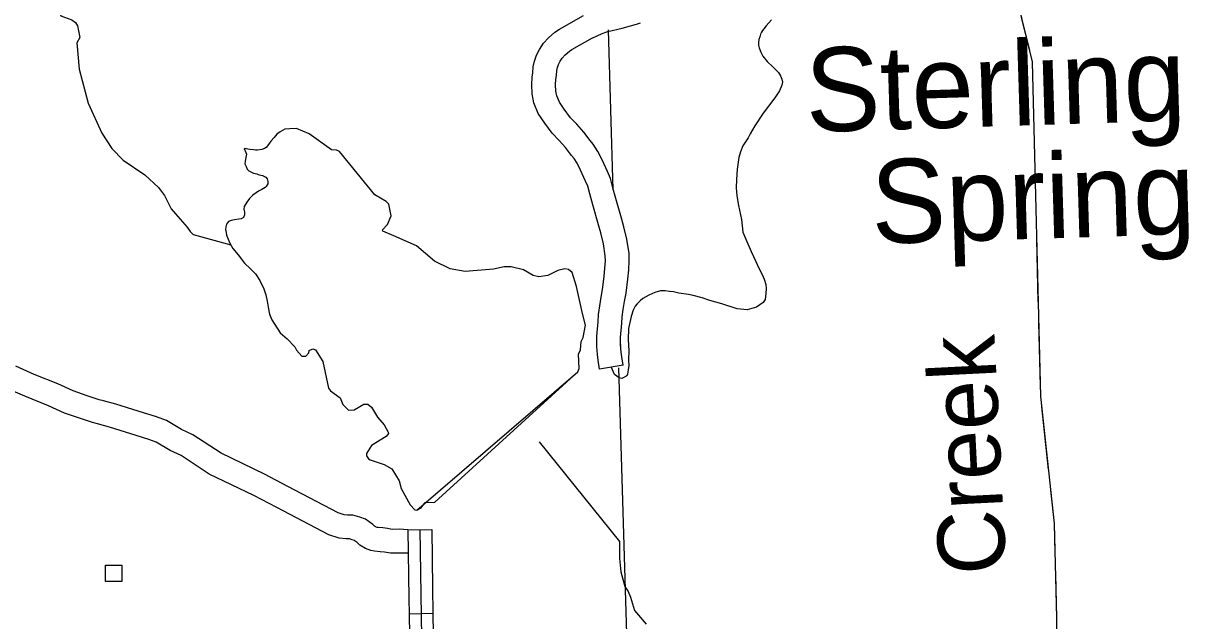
# Model space of a CAD drawing. Extents: x 1671357 to 13005564, y 567358 to 14261451.
# Drawn here: x 12758310.69 to 12758324.59, y 14259899.82 to 14259906.94 of the extents above; entities that cross this region are included whole.
import ezdxf

# ---------------------------------------------------------------- set-up
doc = ezdxf.new("R2010")
doc.units = 0
for name, color, linetype in [('24', 7, 'Continuous'), ('31', 7, 'Continuous'), ('32', 7, 'Continuous'), ('35', 7, 'Continuous'), ('43', 7, 'Continuous'), ('46', 7, 'Continuous'), ('5', 7, 'Continuous'), ('51', 7, 'Continuous'), ('56', 7, 'Continuous')]:
    doc.layers.add(name, color=color, linetype=linetype)

msp = doc.modelspace()

# ---------------------------------------------------------------- linework, layer by layer
at = {"layer": '31'}
msp.add_lwpolyline([(12758315.41, 14259900.907), (12758315.461, 14259897.56), (12758315.42, 14259897.511), (12758315.341, 14259897.481), (12758313.018, 14259897.398), (12758306.475, 14259897.154)], dxfattribs=at)
at = {"layer": '32'}
for p, q in [((12758315.267, 14259900.905), (12758315.552, 14259900.91)), ((12758315.283, 14259899.905), (12758315.567, 14259899.91))]:
    msp.add_line(p, q, dxfattribs=at)
for points in [[(12758315.267, 14259900.905), (12758315.28, 14259900.085)], [(12758315.552, 14259900.91), (12758315.562, 14259900.211)], [(12758315.562, 14259900.211), (12758315.567, 14259899.91)], [(12758315.28, 14259900.085), (12758315.283, 14259899.905)], [(12758315.567, 14259899.91), (12758315.582, 14259898.912)], [(12758315.283, 14259899.905), (12758315.295, 14259899.137)]]:
    msp.add_lwpolyline(points, dxfattribs=at)
at = {"layer": '35'}
for points in [[(12758311.037, 14259907.136), (12758311.075, 14259907.128), (12758311.111, 14259907.092), (12758311.132, 14259907.028), (12758311.263, 14259906.98), (12758311.308, 14259906.948), (12758311.333, 14259906.911), (12758311.357, 14259906.772), (12758311.324, 14259906.709), (12758311.349, 14259906.393), (12758311.457, 14259905.987), (12758311.62, 14259905.631), (12758311.741, 14259905.45), (12758311.874, 14259905.311), (12758312.134, 14259905.134), (12758312.297, 14259904.983), (12758312.366, 14259904.887), (12758312.448, 14259904.731), (12758312.498, 14259904.669), (12758312.64, 14259904.509), (12758312.672, 14259904.459), (12758312.708, 14259904.423), (12758313.16, 14259904.299)], [(12758314.092, 14259905.624), (12758313.94, 14259905.685), (12758313.863, 14259905.683), (12758313.804, 14259905.677), (12758313.745, 14259905.646), (12758313.708, 14259905.618), (12758313.673, 14259905.581), (12758313.635, 14259905.537), (12758313.608, 14259905.496), (12758313.578, 14259905.459), (12758313.559, 14259905.449), (12758313.529, 14259905.438), (12758313.476, 14259905.427), (12758313.452, 14259905.428), (12758313.429, 14259905.431), (12758313.385, 14259905.436), (12758313.316, 14259905.447), (12758313.339, 14259905.402), (12758313.346, 14259905.38), (12758313.338, 14259905.341), (12758313.328, 14259905.299), (12758313.325, 14259905.265), (12758313.34, 14259905.235), (12758313.353, 14259905.2), (12758313.374, 14259905.181), (12758313.403, 14259905.167), (12758313.428, 14259905.155), (12758313.467, 14259905.147), (12758313.486, 14259905.14), (12758313.515, 14259905.132), (12758313.536, 14259905.127), (12758313.549, 14259905.122), (12758313.561, 14259905.116), (12758313.576, 14259905.108), (12758313.59, 14259905.087), (12758313.599, 14259905.053), (12758313.598, 14259905.027), (12758313.581, 14259904.996), (12758313.568, 14259904.984), (12758313.529, 14259904.958), (12758313.49, 14259904.939), (12758313.46, 14259904.921), (12758313.422, 14259904.893), (12758313.381, 14259904.853), (12758313.349, 14259904.81), (12758313.319, 14259904.756), (12758313.314, 14259904.725), (12758313.32, 14259904.689), (12758313.321, 14259904.657), (12758313.311, 14259904.624), (12758313.283, 14259904.61), (12758313.255, 14259904.605), (12758313.204, 14259904.599), (12758313.181, 14259904.596), (12758313.162, 14259904.592), (12758313.132, 14259904.577), (12758313.107, 14259904.548), (12758313.107, 14259904.546), (12758313.097, 14259904.515), (12758313.094, 14259904.483), (12758313.102, 14259904.447), (12758313.108, 14259904.415), (12758313.126, 14259904.366), (12758313.146, 14259904.322), (12758313.183, 14259904.258), (12758313.245, 14259904.181), (12758313.322, 14259904.083), (12758313.391, 14259904.016), (12758313.415, 14259903.992), (12758313.453, 14259903.954), (12758313.503, 14259903.876), (12758313.55, 14259903.777), (12758313.576, 14259903.704), (12758313.59, 14259903.628), (12758313.603, 14259903.557), (12758313.621, 14259903.474), (12758313.648, 14259903.408), (12758313.748, 14259903.253), (12758313.829, 14259903.18)], [(12758314.092, 14259905.624), (12758313.94, 14259905.685), (12758313.863, 14259905.683), (12758313.804, 14259905.677), (12758313.745, 14259905.646), (12758313.708, 14259905.618), (12758313.673, 14259905.581), (12758313.635, 14259905.537), (12758313.608, 14259905.496), (12758313.578, 14259905.459), (12758313.559, 14259905.449), (12758313.529, 14259905.438), (12758313.476, 14259905.427), (12758313.452, 14259905.428), (12758313.429, 14259905.431), (12758313.385, 14259905.436), (12758313.316, 14259905.447), (12758313.339, 14259905.402), (12758313.346, 14259905.38), (12758313.338, 14259905.341), (12758313.328, 14259905.299), (12758313.325, 14259905.265), (12758313.34, 14259905.235), (12758313.353, 14259905.2), (12758313.374, 14259905.181), (12758313.403, 14259905.167), (12758313.428, 14259905.155), (12758313.467, 14259905.147), (12758313.486, 14259905.14), (12758313.515, 14259905.132), (12758313.536, 14259905.127), (12758313.549, 14259905.122), (12758313.561, 14259905.116), (12758313.576, 14259905.108), (12758313.59, 14259905.087), (12758313.599, 14259905.053), (12758313.598, 14259905.027), (12758313.581, 14259904.996), (12758313.568, 14259904.984), (12758313.529, 14259904.958), (12758313.49, 14259904.939), (12758313.46, 14259904.921), (12758313.422, 14259904.893), (12758313.381, 14259904.853), (12758313.349, 14259904.81), (12758313.319, 14259904.756), (12758313.314, 14259904.725), (12758313.32, 14259904.689), (12758313.321, 14259904.657), (12758313.311, 14259904.624), (12758313.283, 14259904.61), (12758313.255, 14259904.605), (12758313.204, 14259904.599), (12758313.181, 14259904.596), (12758313.162, 14259904.592), (12758313.132, 14259904.577), (12758313.107, 14259904.548), (12758313.107, 14259904.546), (12758313.097, 14259904.515), (12758313.094, 14259904.483), (12758313.102, 14259904.447), (12758313.108, 14259904.415), (12758313.126, 14259904.366), (12758313.146, 14259904.322), (12758313.183, 14259904.258), (12758313.245, 14259904.181), (12758313.322, 14259904.083), (12758313.391, 14259904.016), (12758313.415, 14259903.992), (12758313.453, 14259903.954), (12758313.503, 14259903.876), (12758313.55, 14259903.777), (12758313.576, 14259903.704), (12758313.59, 14259903.628), (12758313.603, 14259903.557), (12758313.621, 14259903.474), (12758313.648, 14259903.408), (12758313.748, 14259903.253), (12758313.829, 14259903.18)], [(12758316.646, 14259904.002), (12758316.501, 14259904.04), (12758316.417, 14259904.038), (12758316.288, 14259904.012), (12758315.95, 14259903.981), (12758315.772, 14259904.013), (12758315.586, 14259904.104), (12758315.373, 14259904.289), (12758315.103, 14259904.407), (12758314.97, 14259904.464), (12758314.967, 14259904.479), (12758315.025, 14259904.544), (12758315.068, 14259904.645), (12758315.04, 14259904.786), (12758315.01, 14259904.817), (12758314.874, 14259904.897), (12758314.454, 14259905.413), (12758314.417, 14259905.427), (12758314.36, 14259905.434), (12758314.094, 14259905.623)], [(12758315.035, 14259902.068), (12758315.037, 14259902.051), (12758315.008, 14259902.015), (12758314.833, 14259901.909), (12758314.774, 14259901.812), (12758314.777, 14259901.785), (12758314.798, 14259901.75), (12758314.819, 14259901.738), (12758314.984, 14259901.682), (12758315.076, 14259901.632), (12758315.163, 14259901.486), (12758315.19, 14259901.398), (12758315.295, 14259901.203), (12758315.35, 14259901.142), (12758315.377, 14259901.14), (12758315.427, 14259901.165), (12758315.476, 14259901.231), (12758315.591, 14259901.232), (12758317.293, 14259902.787), (12758317.31, 14259902.827), (12758317.303, 14259902.996), (12758317.324, 14259903.048), (12758317.335, 14259903.148), (12758317.359, 14259903.196), (12758317.385, 14259903.343), (12758317.349, 14259903.482), (12758317.279, 14259903.804), (12758317.226, 14259903.969), (12758317.183, 14259904.006), (12758317.139, 14259904.013), (12758317.054, 14259903.994), (12758316.937, 14259903.936), (12758316.828, 14259903.919), (12758316.763, 14259903.933), (12758316.646, 14259904.002)], [(12758313.829, 14259903.18), (12758313.923, 14259903.083), (12758313.943, 14259903.046), (12758314.005, 14259902.973), (12758314.052, 14259902.975), (12758314.088, 14259903.014), (12758314.093, 14259903.041), (12758314.134, 14259903.062), (12758314.169, 14259903.05), (12758314.254, 14259902.911), (12758314.321, 14259902.591), (12758314.345, 14259902.561), (12758314.462, 14259902.477), (12758314.495, 14259902.398), (12758314.561, 14259902.329), (12758314.627, 14259902.336), (12758314.742, 14259902.401), (12758314.793, 14259902.401), (12758314.836, 14259902.365), (12758314.908, 14259902.248), (12758314.985, 14259902.155), (12758315.035, 14259902.068)], [(12758315.377, 14259901.14), (12758317.293, 14259902.787)], [(12758316.835, 14259901.951), (12758317.789, 14259900.765), (12758317.792, 14259900.564), (12758317.808, 14259900.403), (12758317.856, 14259900.229), (12758317.892, 14259900.171), (12758317.922, 14259900.102), (12758317.968, 14259899.941), (12758318.108, 14259899.779)]]:
    msp.add_lwpolyline(points, dxfattribs=at)
at = {"layer": '43'}
for points in [[(12758322.566, 14259916.542), (12758322.654, 14259912.239), (12758322.632, 14259911.818), (12758322.654, 14259911.202), (12758322.633, 14259910.938), (12758322.52, 14259910.503), (12758322.443, 14259910.313), (12758322.307, 14259909.791), (12758322.287, 14259909.64), (12758322.308, 14259909.327), (12758322.27, 14259908.955), (12758322.296, 14259908.801), (12758322.362, 14259908.532), (12758322.443, 14259907.566), (12758322.708, 14259906.481), (12758322.806, 14259902.494), (12758322.97, 14259900.978), (12758322.998, 14259899.856), (12758322.991, 14259898.857)], [(12758322.497, 14259907.343), (12758322.676, 14259906.615)], [(12758322.76, 14259904.369), (12758322.769, 14259903.994)], [(12758322.769, 14259903.994), (12758322.778, 14259903.619)], [(12758322.784, 14259903.369), (12758322.803, 14259902.619)], [(12758322.819, 14259902.37), (12758322.9, 14259901.624)], [(12758322.927, 14259901.376), (12758322.97, 14259900.978), (12758322.979, 14259900.628)], [(12758322.985, 14259900.378), (12758322.998, 14259899.856), (12758322.997, 14259899.628)]]:
    msp.add_lwpolyline(points, dxfattribs=at)
at = {"layer": '46'}
for p, q in [((12758317.804, 14259903.112), (12758317.804, 14259903.101)), ((12758317.52, 14259903.09), (12758317.52, 14259903.101))]:
    msp.add_line(p, q, dxfattribs=at)
for points in [[(12758317.52, 14259903.101), (12758317.52, 14259903.21), (12758317.536, 14259903.384), (12758317.539, 14259903.47), (12758317.555, 14259903.574), (12758317.571, 14259903.675), (12758317.589, 14259903.768), (12758317.609, 14259903.923), (12758317.617, 14259904.023), (12758317.623, 14259904.108), (12758317.62, 14259904.17), (12758317.599, 14259904.311), (12758317.567, 14259904.444), (12758317.54, 14259904.54), (12758317.471, 14259904.778), (12758317.437, 14259904.908), (12758317.414, 14259904.999), (12758317.387, 14259905.058), (12758317.327, 14259905.189), (12758317.286, 14259905.272), (12758317.249, 14259905.329), (12758317.218, 14259905.364), (12758317.147, 14259905.461), (12758317.071, 14259905.545), (12758316.99, 14259905.631), (12758316.899, 14259905.749), (12758316.823, 14259905.864), (12758316.768, 14259905.994), (12758316.749, 14259906.101), (12758316.744, 14259906.21), (12758316.749, 14259906.3), (12758316.756, 14259906.349), (12758316.763, 14259906.422), (12758316.778, 14259906.49), (12758316.803, 14259906.561), (12758316.836, 14259906.628), (12758316.883, 14259906.702), (12758316.945, 14259906.767), (12758317.021, 14259906.836), (12758317.077, 14259906.872), (12758317.362, 14259907.032)], [(12758317.804, 14259903.101), (12758317.804, 14259903.197), (12758317.82, 14259903.366), (12758317.822, 14259903.443), (12758317.836, 14259903.53), (12758317.851, 14259903.625), (12758317.87, 14259903.723), (12758317.891, 14259903.893), (12758317.901, 14259904.002), (12758317.907, 14259904.104), (12758317.904, 14259904.197), (12758317.878, 14259904.366), (12758317.842, 14259904.516), (12758317.813, 14259904.619), (12758317.745, 14259904.854), (12758317.712, 14259904.98), (12758317.683, 14259905.092), (12758317.646, 14259905.175), (12758317.583, 14259905.312), (12758317.533, 14259905.412), (12758317.477, 14259905.5), (12758317.44, 14259905.542), (12758317.367, 14259905.641), (12758317.281, 14259905.737), (12758317.207, 14259905.815), (12758317.13, 14259905.915), (12758317.074, 14259906), (12758317.042, 14259906.076), (12758317.032, 14259906.131), (12758317.029, 14259906.208), (12758317.033, 14259906.274), (12758317.038, 14259906.317), (12758317.044, 14259906.377), (12758317.052, 14259906.413), (12758317.065, 14259906.45), (12758317.084, 14259906.487), (12758317.108, 14259906.526), (12758317.144, 14259906.564), (12758317.193, 14259906.609), (12758317.222, 14259906.627), (12758317.467, 14259906.765), (12758317.472, 14259906.766), (12758317.524, 14259906.79), (12758317.585, 14259906.819), (12758317.65, 14259906.844), (12758317.822, 14259906.883), (12758317.921, 14259906.911), (12758317.992, 14259906.93), (12758318.042, 14259906.944)], [(12758317.835, 14259902.866), (12758317.818, 14259902.966), (12758317.811, 14259903.023), (12758317.804, 14259903.112)], [(12758317.835, 14259902.866), (12758317.554, 14259902.82), (12758317.537, 14259902.925), (12758317.528, 14259902.993), (12758317.52, 14259903.09)], [(12758315.267, 14259900.905), (12758315.164, 14259900.912), (12758315.08, 14259900.91), (12758315.027, 14259900.918), (12758314.968, 14259900.926), (12758314.915, 14259900.93), (12758314.904, 14259900.933), (12758314.884, 14259900.939), (12758314.871, 14259900.947), (12758314.85, 14259900.968), (12758314.809, 14259901), (12758314.762, 14259901.032), (12758314.694, 14259901.056), (12758314.612, 14259901.08), (12758314.549, 14259901.079), (12758314.509, 14259901.084), (12758314.436, 14259901.108), (12758313.839, 14259901.421), (12758313.56, 14259901.567), (12758313.042, 14259901.817), (12758312.705, 14259902.036), (12758312.57, 14259902.101), (12758312.39, 14259902.208), (12758312.273, 14259902.249), (12758312.054, 14259902.319), (12758311.789, 14259902.402), (12758311.641, 14259902.44), (12758311.59, 14259902.454), (12758311.445, 14259902.502), (12758311.281, 14259902.559), (12758311.097, 14259902.642), (12758310.815, 14259902.756), (12758310.596, 14259902.853)], [(12758315.272, 14259900.625), (12758315.163, 14259900.628), (12758315.062, 14259900.626), (12758314.989, 14259900.636), (12758314.937, 14259900.643), (12758314.869, 14259900.649), (12758314.826, 14259900.659), (12758314.762, 14259900.68), (12758314.697, 14259900.722), (12758314.663, 14259900.753), (12758314.641, 14259900.771), (12758314.634, 14259900.776), (12758314.606, 14259900.786), (12758314.572, 14259900.795), (12758314.533, 14259900.795), (12758314.448, 14259900.805), (12758314.325, 14259900.845), (12758313.707, 14259901.169), (12758313.432, 14259901.313), (12758312.902, 14259901.569), (12758312.566, 14259901.788), (12758312.435, 14259901.85), (12758312.269, 14259901.949), (12758312.183, 14259901.98), (12758311.968, 14259902.048), (12758311.711, 14259902.128), (12758311.568, 14259902.166), (12758311.508, 14259902.182), (12758311.353, 14259902.233), (12758311.175, 14259902.295), (12758310.985, 14259902.38), (12758310.704, 14259902.495), (12758310.472, 14259902.597)]]:
    msp.add_lwpolyline(points, dxfattribs=at)
at = {"layer": '5'}
for points in [[(12758317.717, 14259904.955), (12758317.66, 14259906.861)], [(12758318.076, 14259892.695), (12758317.941, 14259897.546), (12758317.781, 14259902.835)]]:
    msp.add_lwpolyline(points, dxfattribs=at)
at = {"layer": '51'}
msp.add_lwpolyline([(12758319.601, 14259906.981), (12758319.538, 14259906.909), (12758319.509, 14259906.873), (12758319.496, 14259906.856), (12758319.482, 14259906.834), (12758319.47, 14259906.809), (12758319.463, 14259906.78), (12758319.451, 14259906.746), (12758319.447, 14259906.711), (12758319.448, 14259906.681), (12758319.455, 14259906.649), (12758319.474, 14259906.596), (12758319.499, 14259906.548), (12758319.549, 14259906.483), (12758319.617, 14259906.423), (12758319.659, 14259906.383), (12758319.685, 14259906.352), (12758319.711, 14259906.313), (12758319.725, 14259906.276), (12758319.733, 14259906.238), (12758319.726, 14259906.202), (12758319.699, 14259906.134), (12758319.641, 14259906.052), (12758319.502, 14259905.87), (12758319.404, 14259905.72), (12758319.347, 14259905.623), (12758319.323, 14259905.574), (12758319.262, 14259905.479), (12758319.231, 14259905.407), (12758319.214, 14259905.342), (12758319.191, 14259905.202), (12758319.183, 14259905.079), (12758319.181, 14259904.978), (12758319.19, 14259904.883), (12758319.21, 14259904.77), (12758319.245, 14259904.602), (12758319.26, 14259904.453), (12758319.296, 14259904.367), (12758319.36, 14259904.219), (12758319.416, 14259904.102), (12758319.453, 14259904.023), (12758319.491, 14259903.945), (12758319.513, 14259903.893), (12758319.533, 14259903.829), (12758319.539, 14259903.778), (12758319.535, 14259903.721), (12758319.525, 14259903.648), (12758319.504, 14259903.613), (12758319.422, 14259903.559), (12758319.312, 14259903.526), (12758319.192, 14259903.538), (12758319.009, 14259903.598), (12758318.869, 14259903.638), (12758318.775, 14259903.668), (12758318.668, 14259903.695), (12758318.613, 14259903.708), (12758318.498, 14259903.724), (12758318.433, 14259903.739), (12758318.386, 14259903.746), (12758318.336, 14259903.752), (12758318.279, 14259903.754), (12758318.21, 14259903.734), (12758318.141, 14259903.701), (12758318.067, 14259903.66), (12758318.037, 14259903.632), (12758318.003, 14259903.597), (12758317.977, 14259903.571), (12758317.955, 14259903.523), (12758317.929, 14259903.446), (12758317.899, 14259903.304), (12758317.892, 14259903.174), (12758317.902, 14259903.036), (12758317.898, 14259902.928), (12758317.901, 14259902.859), (12758317.895, 14259902.816), (12758317.891, 14259902.781), (12758317.886, 14259902.76), (12758317.879, 14259902.741), (12758317.818, 14259902.708), (12758317.785, 14259902.714), (12758317.729, 14259902.754), (12758317.695, 14259902.84), (12758317.695, 14259902.841)], dxfattribs=at)
at = {"layer": '56'}
msp.add_lwpolyline([(12758311.664, 14259900.288), (12758311.664, 14259900.485), (12758311.861, 14259900.485), (12758311.861, 14259900.288)], close=True, dxfattribs=at)

# ---------------------------------------------------------------- texts
at = {"layer": '24'}
for s, p in [('Sterling', (12758320.02, 14259905.643)), ('Spring', (12758320.802, 14259904.312))]:
    msp.add_text(s, height=1.0001, rotation=1.7629, dxfattribs=at).set_placement(p)
at = {"layer": '35'}
msp.add_text('Creek', height=0.8001, rotation=92.8624, dxfattribs=at).set_placement((12758322.401, 14259900.389))

doc.saveas('drawing.dxf')
